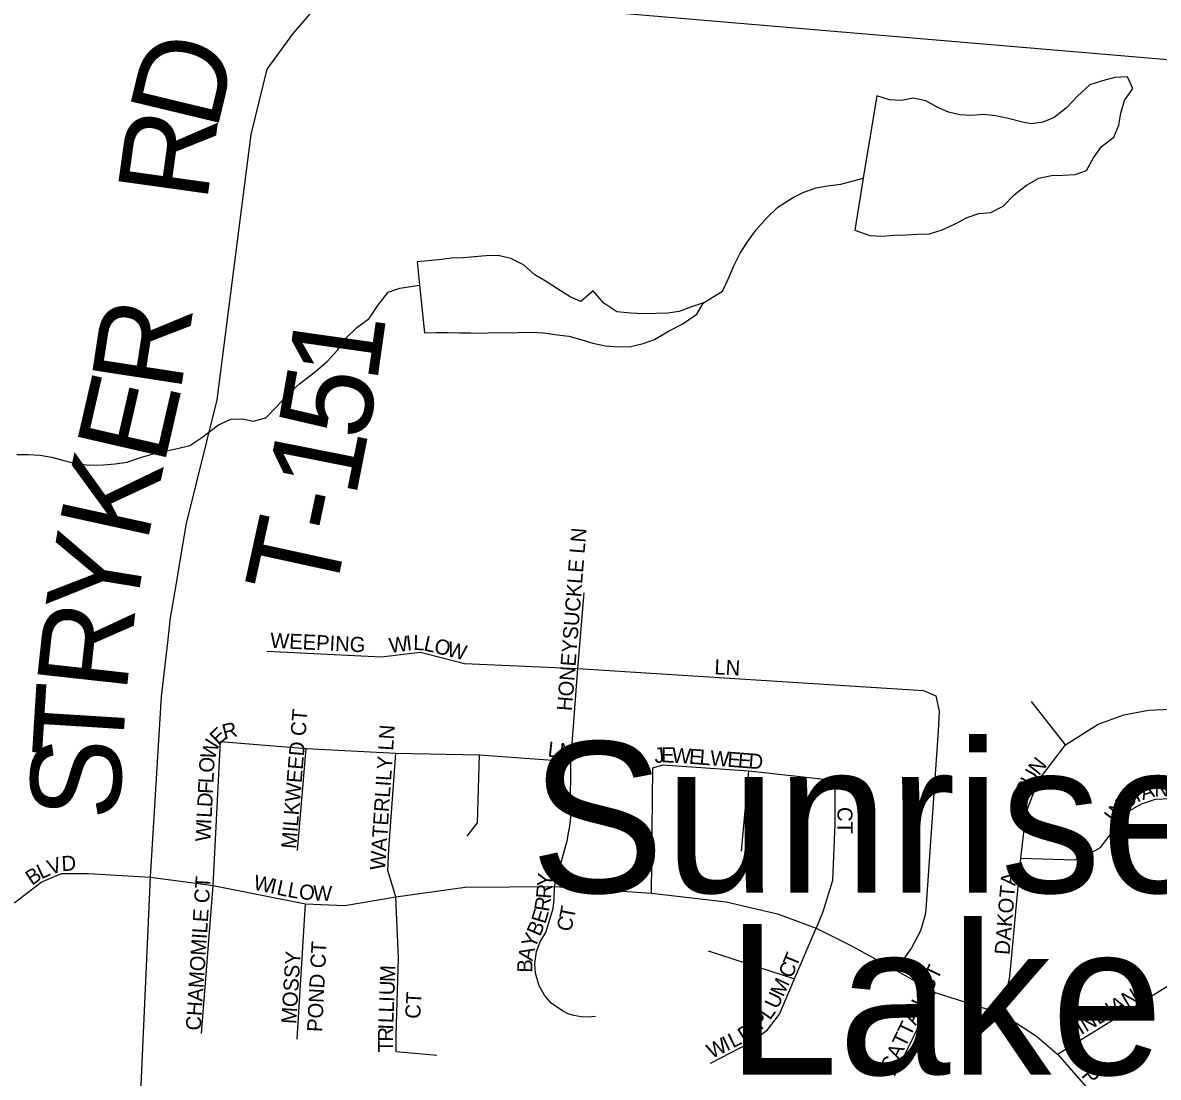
# Model space of a CAD drawing. Extents: x 0 to 34, y -4 to 22.
# Drawn here: x 4.559 to 5.062, y 16.118 to 16.585 of the extents above; entities that cross this region are included whole.
import ezdxf

# ---------------------------------------------------------------- set-up
doc = ezdxf.new("R2010")
doc.units = 0
for name, color, linetype in [('GM_X_County_Road', 7, 'Continuous'), ('GM_X_Minor_Lake', 7, 'Continuous'), ('GM_X_Minor_Lake_Text', 7, 'Continuous'), ('GM_X_Minor_River', 7, 'Continuous'), ('GM_X_Township_Road', 7, 'Continuous'), ('GM_X_Township_Road_Text', 7, 'Continuous'), ('GM_X_Township_Subdivision', 7, 'Continuous'), ('GM_X_Township_Subdivision_Text', 7, 'Continuous')]:
    doc.layers.add(name, color=color, linetype=linetype)

msp = doc.modelspace()

# ---------------------------------------------------------------- linework, layer by layer
at = {"layer": 'GM_X_County_Road'}
msp.add_lwpolyline([(4.47335, 16.84784), (4.47536, 16.84296), (4.47917, 16.83821), (4.48559, 16.83869), (4.49665, 16.84107), (4.50484, 16.84178), (4.51138, 16.83833), (4.51409, 16.8342), (4.52284, 16.81127), (4.54744, 16.75104), (4.55974, 16.73095), (4.56894, 16.71521), (4.57718, 16.70351), (4.60715, 16.6843), (4.61642, 16.67097), (4.66813, 16.62719), (4.69678, 16.60086), (4.79649, 16.59125), (5.3612, 16.54336)], dxfattribs=at)
at = {"layer": 'GM_X_Minor_Lake'}
for points in [[(4.92724, 16.49287), (4.93389, 16.49063), (4.9395, 16.49027), (4.94459, 16.49072), (4.94994, 16.49091), (4.95502, 16.49109), (4.96038, 16.49128), (4.96602, 16.49306), (4.97142, 16.49564), (4.97708, 16.49849), (4.98219, 16.50028), (4.98755, 16.50073), (4.99295, 16.50359), (4.99785, 16.50859), (5.00327, 16.51278), (5.00867, 16.5159), (5.01431, 16.51715), (5.0194, 16.51733), (5.02475, 16.51752), (5.02986, 16.51931), (5.0329, 16.52487), (5.03646, 16.5299), (5.04188, 16.53408), (5.04411, 16.5394), (5.045, 16.54473), (5.0467, 16.55032), (5.05027, 16.5556), (5.04794, 16.56072), (5.04232, 16.56054), (5.03695, 16.55902), (5.0313, 16.55724), (5.02587, 16.55225), (5.02096, 16.54698), (5.01554, 16.54279), (5.01043, 16.54073), (5.00533, 16.54001), (5.00157, 16.54067)], [(5.00157, 16.54067), (4.99521, 16.54231), (4.98961, 16.54347), (4.98427, 16.54409), (4.97891, 16.54364), (4.97383, 16.54399), (4.96877, 16.54514), (4.96373, 16.54736), (4.95869, 16.55011), (4.95309, 16.55127), (4.94799, 16.55028), (4.94265, 16.55064), (4.93706, 16.55233), (4.93105, 16.51594)], [(4.93105, 16.51594), (4.92724, 16.49287)], [(4.80134, 16.46347), (4.79573, 16.4669), (4.7907, 16.47019), (4.78567, 16.47321), (4.78066, 16.47756), (4.77509, 16.48033), (4.7695, 16.48175), (4.76414, 16.48157), (4.75905, 16.48112), (4.75396, 16.48066), (4.74861, 16.48048), (4.74325, 16.47976), (4.7336, 16.47885)], [(4.7336, 16.47885), (4.73466, 16.46856)], [(4.73466, 16.46856), (4.73682, 16.44752), (4.74191, 16.44771), (4.74699, 16.44763), (4.75234, 16.44754), (4.75742, 16.44746), (4.7625, 16.44738), (4.76759, 16.44757), (4.7732, 16.44748), (4.77829, 16.44766), (4.78391, 16.44784), (4.78952, 16.44748), (4.79566, 16.44658), (4.80073, 16.44597), (4.80605, 16.44455), (4.81138, 16.44286), (4.81697, 16.4417), (4.82258, 16.44134), (4.8282, 16.44152), (4.83357, 16.44277), (4.83869, 16.44456), (4.8449, 16.4482), (4.85084, 16.45132), (4.85733, 16.45576), (4.86036, 16.46079)], [(4.86036, 16.46079), (4.85498, 16.459), (4.8496, 16.45695), (4.8445, 16.45623), (4.83942, 16.45604), (4.83379, 16.45587), (4.82818, 16.45622), (4.82204, 16.45686), (4.81622, 16.46069), (4.8115, 16.46611), (4.80607, 16.46139), (4.80134, 16.46347)]]:
    msp.add_lwpolyline(points, dxfattribs=at)
at = {"layer": 'GM_X_Minor_River'}
for points in [[(4.86036, 16.46079), (4.86874, 16.466), (4.87124, 16.47131), (4.87374, 16.47715), (4.87651, 16.48272), (4.8798, 16.48775), (4.88364, 16.49303), (4.888, 16.49804), (4.89317, 16.50304), (4.89966, 16.50721), (4.90478, 16.5098), (4.91016, 16.51159), (4.91526, 16.51258), (4.92116, 16.51329), (4.93105, 16.51594)], [(4.55643, 16.39372), (4.56152, 16.39364), (4.56659, 16.3933), (4.57193, 16.39241), (4.57725, 16.39099), (4.58311, 16.38956), (4.58872, 16.38893), (4.59487, 16.3891), (4.59997, 16.38955), (4.60533, 16.39027), (4.61125, 16.39232), (4.61635, 16.39384), (4.62199, 16.39508), (4.62763, 16.39633), (4.633, 16.39758), (4.63841, 16.40124), (4.64573, 16.40674), (4.65112, 16.40932), (4.65621, 16.40951), (4.66127, 16.40836), (4.66664, 16.40988), (4.67154, 16.41488), (4.67617, 16.41988), (4.68161, 16.42488), (4.68784, 16.42986), (4.69381, 16.43484), (4.69844, 16.43985), (4.70174, 16.44487), (4.70691, 16.44987), (4.71232, 16.45379), (4.71616, 16.45961), (4.72081, 16.46542), (4.72592, 16.46721), (4.73466, 16.46856)]]:
    msp.add_lwpolyline(points, dxfattribs=at)
at = {"layer": 'GM_X_Township_Road'}
msp.add_lwpolyline([(4.60934, 16.06527), (4.61566, 16.20669), (4.62049, 16.28658), (4.62332, 16.31041), (4.62453, 16.32132), (4.62695, 16.33586), (4.6314, 16.36251), (4.64513, 16.41785), (4.66019, 16.53523), (4.6672, 16.56417), (4.67886, 16.58004), (4.69678, 16.60086)], dxfattribs=at)
at = {"layer": 'GM_X_Township_Subdivision'}
for points in [[(4.7944, 16.20255), (4.80011, 16.22328), (4.80078, 16.22722), (4.80106, 16.22824), (4.80126, 16.22957), (4.80154, 16.23142), (4.80164, 16.23326), (4.80157, 16.23444), (4.80147, 16.23593), (4.80156, 16.25786), (4.80466, 16.29898), (4.80753, 16.33247)], [(4.66714, 16.30657), (4.71783, 16.30415), (4.72752, 16.30536), (4.735, 16.30617), (4.74479, 16.30364), (4.75458, 16.30112), (4.80466, 16.29898), (4.95775, 16.28924), (4.96309, 16.28684), (4.96469, 16.28016), (4.96416, 16.27135), (4.95868, 16.19242), (4.95838, 16.18994), (4.95642, 16.18282), (4.95241, 16.17534), (4.94545, 16.16554)], [(4.99246, 16.1461), (4.99593, 16.16266), (5.00073, 16.215), (5.00305, 16.23522), (5.00848, 16.24932), (5.02049, 16.26521), (5.03491, 16.27429), (5.04639, 16.27842), (5.05728, 16.28049), (5.07023, 16.28109), (5.09793, 16.28118), (5.14813, 16.27663)], [(5.02049, 16.26521), (5.00554, 16.28444)], [(5.01702, 16.12834), (5.11548, 16.18918), (5.1203, 16.19175), (5.12995, 16.19336), (5.20809, 16.20654), (5.21999, 16.21073), (5.2261, 16.21844), (5.22996, 16.22552), (5.2306, 16.23934), (5.23157, 16.27247), (5.18848, 16.27536), (5.18558, 16.23549)], [(4.64337, 16.20295), (4.64662, 16.26668), (4.68457, 16.26362), (4.72426, 16.26151), (4.76123, 16.26084), (4.80156, 16.25786)], [(4.68071, 16.21844), (4.68457, 16.26362)], [(4.72425, 16.19799), (4.72058, 16.20954), (4.72111, 16.2191), (4.72426, 16.26151)], [(4.75573, 16.22475), (4.76035, 16.23073), (4.76123, 16.26084)], [(4.83733, 16.19958), (4.83787, 16.25506), (4.84241, 16.2564), (4.88033, 16.25372), (4.91637, 16.24972), (4.9185, 16.24651), (4.9185, 16.23022), (4.91744, 16.20512), (4.91317, 16.19123), (4.91015, 16.18411)], [(4.87712, 16.21821), (4.88033, 16.25372)], [(5.00073, 16.215), (5.02466, 16.21437), (5.03061, 16.21662), (5.03598, 16.21981), (5.04506, 16.23156), (5.04933, 16.23623), (5.05418, 16.23915), (5.06039, 16.24113), (5.06695, 16.24139), (5.17015, 16.23356), (5.18558, 16.23549), (5.21163, 16.24031), (5.2306, 16.23934)], [(4.50499, 16.19078), (4.50741, 16.19042), (4.52469, 16.18631), (4.54115, 16.1885), (4.55568, 16.19564), (4.5672, 16.20441), (4.57626, 16.20825), (4.58805, 16.20825), (4.61566, 16.20669)], [(4.61566, 16.20669), (4.64337, 16.20295), (4.68417, 16.1949), (4.70155, 16.19416), (4.72425, 16.19799), (4.75482, 16.20217), (4.7944, 16.20255), (4.83733, 16.19958), (4.8703, 16.19566), (4.89314, 16.19043), (4.91015, 16.18411), (4.92583, 16.17623), (4.94545, 16.16554), (4.96283, 16.15558), (4.99246, 16.1461), (5.00768, 16.13635), (5.01702, 16.12834), (5.03155, 16.11168), (5.04579, 16.08836)], [(4.63826, 16.13741), (4.64337, 16.20295)], [(4.8126, 16.14494), (4.80928, 16.14463), (4.80626, 16.14479), (4.80289, 16.14546), (4.80048, 16.14622), (4.79795, 16.14743), (4.79299, 16.15093), (4.78994, 16.15449), (4.78765, 16.1585), (4.78594, 16.16409), (4.78568, 16.16829), (4.78641, 16.17376), (4.78807, 16.17808), (4.79061, 16.18215), (4.79377, 16.1928), (4.79422, 16.19687), (4.7944, 16.20255)], [(4.74235, 16.12774), (4.72429, 16.12933), (4.72429, 16.13677), (4.72535, 16.17077), (4.72425, 16.19799)], [(4.68055, 16.13499), (4.68417, 16.1949)], [(4.8635, 16.12433), (4.88112, 16.13341), (4.8886, 16.13902), (4.89394, 16.14596), (4.90054, 16.16163), (4.91015, 16.18411)], [(4.86244, 16.17401), (4.90054, 16.16163)], [(4.94482, 16.11867), (4.96283, 16.15558)]]:
    msp.add_lwpolyline(points, dxfattribs=at)

# ---------------------------------------------------------------- texts
at = {"layer": 'GM_X_Minor_Lake_Text'}
for s, rotation, p in [('Sunrise', 359.9996, (4.7836, 16.19983)), ('Lake', 359.9997, (4.87047, 16.1193))]:
    msp.add_text(s, height=0.066666, rotation=rotation, dxfattribs=at).set_placement(p)
at = {"layer": 'GM_X_Township_Road_Text'}
for s, rotation, p in [('D', 76.4727, (4.64484, 16.53623)), ('R', 82.0554, (4.64049, 16.50471)), ('R', 81.2617, (4.62885, 16.42055)), ('1', 81.9354, (4.71577, 16.42478)), ('E', 77.0324, (4.62153, 16.38823)), ('5', 80.0718, (4.7113, 16.3991)), ('1', 78.807, (4.70634, 16.37398)), ('K', 77.6506, (4.61403, 16.35396)), ('-', 77.9703, (4.70279, 16.3573)), ('T', 77.6915, (4.69637, 16.32786)), ('Y', 80.7066, (4.60845, 16.31977)), ('R', 83.6995, (4.60492, 16.28767)), ('T', 86.4319, (4.6031, 16.25831)), ('S', 86.9625, (4.60168, 16.23146))]:
    msp.add_text(s, height=0.04, rotation=rotation, dxfattribs=at).set_placement(p)
at = {"layer": 'GM_X_Township_Subdivision_Text'}
for s, height, rotation, p in [('HONEYSUCKLE LN', 0.0066667, 85.4243, (4.80211, 16.27996)), ('WEEPING', 0.006667, 357.2313, (4.66849, 16.30815)), ('W', 0.00667, 7.4358, (4.72164, 16.3058)), ('I', 0.00667, 7.4609, (4.72921, 16.30678)), ('L', 0.00667, 358.4969, (4.73184, 16.30715)), ('L', 0.00667, 347.0771, (4.73618, 16.30707)), ('O', 0.00667, 345.8895, (4.74072, 16.30603)), ('W', 0.00667, 345.922, (4.74641, 16.3046)), ('LN', 0.006667, 356.9769, (4.86503, 16.29642)), ('MILKWEED CT', 0.0066667, 85.2856, (4.68009, 16.219)), ('E', 0.00667, 43.5682, (4.64572, 16.26469)), ('R', 0.00667, 14.5228, (4.64835, 16.2675)), ('WATERLILY LN', 0.0066667, 86.1505, (4.7194, 16.20958)), ('W', 0.00667, 72.6137, (4.64391, 16.25817)), ('LN', 0.006667, 353.6518, (4.79118, 16.26004)), ('J', 0.00667, 6.2195, (4.83885, 16.25708)), ('E', 0.00667, 359.7268, (4.84157, 16.25739)), ('W', 0.00667, 356.0797, (4.84615, 16.25737)), ('E', 0.00667, 355.5971, (4.85374, 16.25685)), ('L', 0.00667, 355.594, (4.85842, 16.25649)), ('W', 0.00667, 355.6013, (4.8631, 16.25613)), ('E', 0.00667, 355.5971, (4.8707, 16.25555)), ('E', 0.00667, 355.594, (4.87538, 16.25519)), ('D', 0.00667, 355.5994, (4.88006, 16.25483)), ('O', 0.00667, 87.1365, (4.6437, 16.25275)), ('N', 0.00667, 51.6439, (5.00872, 16.25127)), ('L', 0.00667, 87.1365, (4.64346, 16.24806)), ('U', 0.00667, 61.2447, (5.00606, 16.24637)), ('F', 0.00667, 87.1365, (4.64323, 16.24337)), ('R', 0.00667, 66.4123, (5.00402, 16.24168)), ('I', 0.00667, 24.4729, (5.05224, 16.23958)), ('A', 0.00667, 15.1229, (5.05464, 16.2407)), ('N', 0.00667, 2.6234, (5.05993, 16.24217)), ('D', 0.00667, 87.1365, (4.64293, 16.23751)), ('N', 0.00667, 47.9998, (5.044, 16.23241)), ('D', 0.00667, 33.4719, (5.04759, 16.23648)), ('L', 0.00667, 87.1365, (4.6427, 16.23282)), ('CT', 0.006667, 270, (4.91961, 16.23767)), ('W', 0.00667, 87.1365, (4.64217, 16.22227)), ('I', 0.00667, 87.1365, (4.64255, 16.22989)), ('I', 0.00667, 52.3435, (5.0423, 16.23019)), ('D', 0.00667, 3.0174, (4.57641, 16.20929)), ('B', 0.00667, 33.7507, (4.5631, 16.20278)), ('L', 0.00667, 25.2084, (4.56727, 16.20558)), ('V', 0.00667, 18.5939, (4.57132, 16.20751)), ('CHAMOMILE CT', 0.0066667, 86.2571, (4.63785, 16.13861)), ('W', 0.00667, 347.6209, (4.66078, 16.20129)), ('I', 0.00667, 347.6209, (4.66823, 16.19965)), ('Y', 0.00667, 84.6591, (4.79324, 16.20216)), ('DAKOTA', 0.006667, 85.1551, (4.99572, 16.17207)), ('L', 0.00667, 347.6209, (4.67109, 16.19902)), ('L', 0.00667, 349.684, (4.67593, 16.19796)), ('O', 0.00667, 353.8104, (4.68107, 16.19705)), ('W', 0.00667, 357.9368, (4.68742, 16.19638)), ('R', 0.00667, 85.509, (4.79283, 16.19692)), ('R', 0.00667, 80.8534, (4.79192, 16.19112)), ('E', 0.00667, 72.7153, (4.79029, 16.18564)), ('T', 0.00667, 78.9401, (4.80302, 16.18773)), ('B', 0.00667, 66.9777, (4.78797, 16.18009)), ('C', 0.00667, 74.3082, (4.80146, 16.18207)), ('Y', 0.00667, 66.8186, (4.78566, 16.17468)), ('POND CT', 0.006667, 87.0908, (4.69154, 16.13801)), ('MOSSY', 0.006667, 86.4256, (4.68009, 16.14154)), ('A', 0.00667, 78.9386, (4.78464, 16.16928)), ('T', 0.00667, 67.5781, (4.90145, 16.16641)), ('M', 0.00667, 87.8688, (4.72378, 16.16016)), ('B', 0.00667, 88.251, (4.78451, 16.16429)), ('C', 0.00667, 67.0464, (4.89937, 16.16149)), ('CATTAIL CT', 0.006667, 64.3852, (4.94421, 16.11971)), ('M', 0.00667, 65.291, (4.89562, 16.15328)), ('U', 0.00667, 87.8797, (4.72356, 16.15429)), ('CT', 0.006667, 86.8215, (4.73495, 16.14383)), ('U', 0.00667, 64.3011, (4.89302, 16.14788)), ('INDIAN', 0.006667, 30.7644, (5.02743, 16.13665)), ('L', 0.00667, 87.8688, (4.72328, 16.14667)), ('I', 0.00667, 87.8915, (4.72345, 16.15136)), ('L', 0.00667, 87.8961, (4.72311, 16.14198)), ('P', 0.00667, 46.8387, (4.88588, 16.13877)), ('L', 0.00667, 55.2573, (4.88976, 16.14303)), ('I', 0.00667, 87.9452, (4.723, 16.13905)), ('D', 0.00667, 32.2093, (4.87817, 16.1333)), ('R', 0.00667, 89.0771, (4.72292, 16.13381)), ('W', 0.00667, 26.3019, (4.86385, 16.12617)), ('I', 0.00667, 26.3021, (4.87068, 16.12955)), ('L', 0.00667, 26.3088, (4.87331, 16.13085)), ('T', 0.00667, 89.9453, (4.72291, 16.12914)), ('P', 0.00667, 309.1164, (5.02727, 16.11879))]:
    msp.add_text(s, height=height, rotation=rotation, dxfattribs=at).set_placement(p)

doc.saveas('drawing.dxf')
